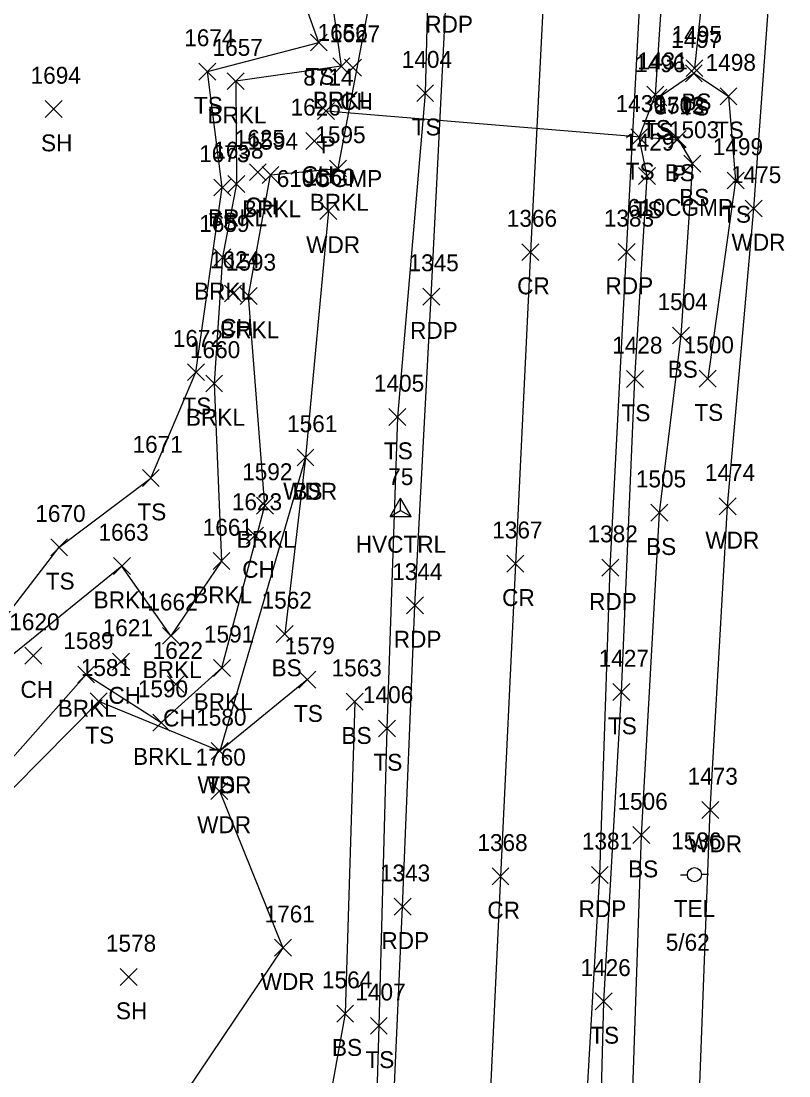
# Model space of a CAD drawing. Extents: x 1482574 to 1485769, y 580696 to 595649.
# Drawn here: x 1485133.4 to 1485224.3, y 582027 to 582151.9 of the extents above; entities that cross this region are included whole.
import ezdxf

# ---------------------------------------------------------------- set-up
doc = ezdxf.new("R2010")
doc.units = 0
for name, color, linetype in [('C_A', 7, 'Continuous'), ('C_I', 7, 'Continuous'), ('CPSM', 7, 'Continuous'), ('D_A', 7, 'Continuous'), ('D_C', 7, 'Continuous'), ('D_I', 7, 'Continuous'), ('D_TIC', 7, 'Continuous'), ('DCP', 7, 'Continuous'), ('L_A', 7, 'Continuous'), ('L_I', 7, 'Continuous'), ('L_TIC', 7, 'Continuous'), ('LAWA', 7, 'Continuous'), ('LAWE', 7, 'Continuous'), ('LELB', 7, 'Continuous'), ('P_A', 7, 'Continuous'), ('P_I', 7, 'Continuous'), ('P_TIC', 7, 'Continuous'), ('PET', 7, 'Continuous'), ('PRC', 7, 'Continuous'), ('U_A', 7, 'Continuous'), ('U_C', 7, 'Continuous'), ('U_I', 7, 'Continuous'), ('UP', 7, 'Continuous')]:
    doc.layers.add(name, color=color, linetype=linetype)

msp = doc.modelspace()

# ---------------------------------------------------------------- linework, layer by layer
at = {"layer": 'CPSM'}
for p, q in [((1485177.11, 582093.23), (1485178.36, 582095.39)), ((1485177.11, 582093.23), (1485178.36, 582095.39)), ((1485177.11, 582093.23), (1485178.36, 582095.39)), ((1485179.61, 582093.23), (1485178.36, 582095.39)), ((1485178.36, 582093.95), (1485178.36, 582095.39)), ((1485179.61, 582093.23), (1485178.36, 582095.39)), ((1485178.36, 582093.95), (1485178.36, 582095.39)), ((1485179.61, 582093.23), (1485178.36, 582095.39)), ((1485178.36, 582093.95), (1485178.36, 582095.39)), ((1485177.11, 582093.23), (1485178.36, 582093.95)), ((1485177.11, 582093.23), (1485178.36, 582093.95)), ((1485177.11, 582093.23), (1485178.36, 582093.95)), ((1485178.36, 582093.95), (1485178.36, 582093.95)), ((1485178.36, 582093.95), (1485179.61, 582093.23)), ((1485178.36, 582093.95), (1485178.36, 582093.95)), ((1485178.36, 582093.95), (1485179.61, 582093.23)), ((1485178.36, 582093.95), (1485178.36, 582093.95)), ((1485178.36, 582093.95), (1485179.61, 582093.23)), ((1485177.11, 582093.23), (1485179.61, 582093.23)), ((1485177.11, 582093.23), (1485179.61, 582093.23)), ((1485177.11, 582093.23), (1485179.61, 582093.23))]:
    msp.add_line(p, q, dxfattribs=at)
at = {"layer": 'D_TIC'}
for points in [[(1485168.54, 582140.23), (1485170.54, 582142.23)], [(1485170.54, 582140.23), (1485168.54, 582142.23)], [(1485210.06, 582136.81), (1485212.06, 582138.81)], [(1485212.06, 582136.81), (1485210.06, 582138.81)]]:
    msp.add_lwpolyline(points, dxfattribs=at)
at = {"layer": 'DCP'}
msp.add_lwpolyline([(1485169.54, 582141.23), (1485211.06, 582137.81)], dxfattribs=at)
at = {"layer": 'L_TIC'}
for points in [[(1485167.69, 582148.33), (1485169.69, 582150.33)], [(1485169.69, 582148.33), (1485167.69, 582150.33)], [(1485170.34, 582145.51), (1485172.34, 582147.51)], [(1485172.34, 582145.51), (1485170.34, 582147.51)], [(1485154.49, 582144.89), (1485156.49, 582146.89)], [(1485156.49, 582144.89), (1485154.49, 582146.89)], [(1485171.72, 582145.36), (1485173.72, 582147.36)], [(1485173.72, 582145.36), (1485171.72, 582147.36)], [(1485212.07, 582144.69), (1485214.07, 582146.69)], [(1485214.07, 582144.69), (1485212.07, 582146.69)], [(1485212.15, 582145.29), (1485214.14, 582147.29)], [(1485214.14, 582145.29), (1485212.15, 582147.29)], [(1485157.85, 582143.75), (1485159.85, 582145.75)], [(1485159.85, 582143.75), (1485157.85, 582145.75)], [(1485180.27, 582142.33), (1485182.27, 582144.33)], [(1485182.27, 582142.33), (1485180.27, 582144.33)], [(1485207.52, 582142.15), (1485209.52, 582144.15)], [(1485209.52, 582142.15), (1485207.52, 582144.15)], [(1485207.87, 582141.82), (1485209.87, 582143.82)], [(1485209.87, 582141.82), (1485207.87, 582143.82)], [(1485216.17, 582141.97), (1485218.17, 582143.97)], [(1485218.17, 582141.97), (1485216.17, 582143.97)], [(1485136.31, 582140.45), (1485138.31, 582142.45)], [(1485138.31, 582140.45), (1485136.31, 582142.45)], [(1485167.14, 582136.68), (1485169.14, 582138.68)], [(1485169.14, 582136.68), (1485167.14, 582138.68)], [(1485205.6, 582137.1), (1485207.6, 582139.1)], [(1485207.6, 582137.1), (1485205.6, 582139.1)], [(1485210.18, 582136.92), (1485212.18, 582138.92)], [(1485212.18, 582136.92), (1485210.18, 582138.92)], [(1485160.47, 582132.98), (1485162.47, 582134.98)], [(1485162.47, 582132.98), (1485160.47, 582134.98)], [(1485169.96, 582133.42), (1485171.96, 582135.42)], [(1485171.96, 582133.42), (1485169.96, 582135.42)], [(1485211.9, 582134), (1485213.9, 582136)], [(1485213.9, 582134), (1485211.9, 582136)], [(1485161.97, 582132.65), (1485163.96, 582134.65)], [(1485163.96, 582132.65), (1485161.97, 582134.65)], [(1485206.53, 582132.53), (1485208.53, 582134.53)], [(1485208.53, 582132.53), (1485206.53, 582134.53)], [(1485217.01, 582132), (1485219.01, 582134)], [(1485219.01, 582132), (1485217.01, 582134)], [(1485156.26, 582131.17), (1485158.26, 582133.17)], [(1485158.26, 582131.17), (1485156.26, 582133.17)], [(1485157.93, 582131.59), (1485159.93, 582133.59)], [(1485159.93, 582131.59), (1485157.93, 582133.59)], [(1485168.82, 582128.4), (1485170.82, 582130.4)], [(1485170.82, 582128.4), (1485168.82, 582130.4)], [(1485219.16, 582128.7), (1485221.16, 582130.69)], [(1485221.16, 582128.7), (1485219.16, 582130.69)], [(1485156.28, 582122.91), (1485158.28, 582124.91)], [(1485158.28, 582122.91), (1485156.28, 582124.91)], [(1485157.53, 582118.62), (1485159.53, 582120.62)], [(1485159.53, 582118.62), (1485157.53, 582120.62)], [(1485159.37, 582118.33), (1485161.37, 582120.33)], [(1485161.37, 582118.33), (1485159.37, 582120.33)], [(1485210.54, 582113.66), (1485212.54, 582115.66)], [(1485212.54, 582113.66), (1485210.54, 582115.66)], [(1485153.14, 582109.31), (1485155.14, 582111.31)], [(1485155.14, 582109.31), (1485153.14, 582111.31)], [(1485155.3, 582107.98), (1485157.3, 582109.98)], [(1485157.3, 582107.98), (1485155.3, 582109.98)], [(1485205.1, 582108.51), (1485207.1, 582110.51)], [(1485207.1, 582108.51), (1485205.1, 582110.51)], [(1485213.72, 582108.55), (1485215.72, 582110.55)], [(1485215.72, 582108.55), (1485213.72, 582110.55)], [(1485176.98, 582104.01), (1485178.98, 582106.01)], [(1485178.98, 582104.01), (1485176.98, 582106.01)], [(1485166.11, 582099.22), (1485168.1, 582101.22)], [(1485168.1, 582099.22), (1485166.11, 582101.22)], [(1485166.11, 582099.22), (1485168.1, 582101.22)], [(1485168.1, 582099.22), (1485166.11, 582101.22)], [(1485147.8, 582096.78), (1485149.8, 582098.78)], [(1485149.8, 582096.78), (1485147.8, 582098.78)], [(1485161.31, 582093.53), (1485163.3, 582095.53)], [(1485163.3, 582093.53), (1485161.31, 582095.53)], [(1485216.07, 582093.44), (1485218.07, 582095.44)], [(1485218.07, 582093.44), (1485216.07, 582095.44)], [(1485207.98, 582092.68), (1485209.98, 582094.68)], [(1485209.98, 582092.68), (1485207.98, 582094.68)], [(1485160.13, 582089.99), (1485162.13, 582091.98)], [(1485162.13, 582089.99), (1485160.13, 582091.98)], [(1485136.95, 582088.59), (1485138.95, 582090.59)], [(1485138.95, 582088.59), (1485136.95, 582090.59)], [(1485156.16, 582086.96), (1485158.16, 582088.96)], [(1485158.16, 582086.96), (1485156.16, 582088.96)], [(1485144.38, 582086.37), (1485146.38, 582088.37)], [(1485146.38, 582086.37), (1485144.38, 582088.37)], [(1485150.18, 582078.12), (1485152.18, 582080.11)], [(1485152.18, 582078.12), (1485150.18, 582080.11)], [(1485163.65, 582078.34), (1485165.65, 582080.33)], [(1485165.65, 582078.34), (1485163.65, 582080.33)], [(1485133.88, 582075.77), (1485135.88, 582077.77)], [(1485135.88, 582075.77), (1485133.88, 582077.77)], [(1485144.28, 582075.07), (1485146.28, 582077.07)], [(1485146.28, 582075.07), (1485144.28, 582077.07)], [(1485156.22, 582074.32), (1485158.22, 582076.32)], [(1485158.22, 582074.32), (1485156.22, 582076.32)], [(1485140.14, 582073.54), (1485142.14, 582075.54)], [(1485142.14, 582073.54), (1485140.14, 582075.54)], [(1485150.76, 582072.39), (1485152.76, 582074.39)], [(1485152.76, 582072.39), (1485150.76, 582074.39)], [(1485166.33, 582072.93), (1485168.33, 582074.93)], [(1485168.33, 582072.93), (1485166.33, 582074.93)], [(1485203.5, 582071.46), (1485205.5, 582073.46)], [(1485205.5, 582071.46), (1485203.5, 582073.46)], [(1485141.63, 582070.36), (1485143.63, 582072.36)], [(1485143.63, 582070.36), (1485141.63, 582072.36)], [(1485171.93, 582070.32), (1485173.93, 582072.32)], [(1485173.93, 582070.32), (1485171.93, 582072.32)], [(1485149.04, 582067.84), (1485151.04, 582069.84)], [(1485151.04, 582067.84), (1485149.04, 582069.84)], [(1485175.74, 582067.15), (1485177.74, 582069.15)], [(1485177.74, 582067.15), (1485175.74, 582069.15)], [(1485155.95, 582064.48), (1485157.95, 582066.48)], [(1485157.95, 582064.48), (1485155.95, 582066.48)], [(1485155.95, 582064.48), (1485157.95, 582066.48)], [(1485157.95, 582064.48), (1485155.95, 582066.48)], [(1485155.92, 582059.76), (1485157.92, 582061.76)], [(1485157.92, 582059.76), (1485155.92, 582061.76)], [(1485214.03, 582057.5), (1485216.03, 582059.5)], [(1485216.03, 582057.5), (1485214.03, 582059.5)], [(1485205.85, 582054.53), (1485207.85, 582056.53)], [(1485207.85, 582054.53), (1485205.85, 582056.53)], [(1485163.44, 582041.2), (1485165.43, 582043.2)], [(1485165.43, 582041.2), (1485163.44, 582043.2)], [(1485145.18, 582037.74), (1485147.18, 582039.74)], [(1485147.18, 582037.74), (1485145.18, 582039.74)], [(1485201.4, 582034.85), (1485203.4, 582036.85)], [(1485203.4, 582034.85), (1485201.4, 582036.85)], [(1485170.8, 582033.4), (1485172.8, 582035.4)], [(1485172.8, 582033.4), (1485170.8, 582035.4)], [(1485174.79, 582031.96), (1485176.79, 582033.96)], [(1485176.79, 582031.96), (1485174.79, 582033.96)]]:
    msp.add_lwpolyline(points, dxfattribs=at)
at = {"layer": 'LAWA'}
for points in [[(1485207.14, 581842.19), (1485209.3, 581873.94), (1485212.4, 581914.05), (1485215, 581947.41), (1485214.38, 581982.49), (1485213.5, 582018.76), (1485215.02, 582058.5), (1485217.07, 582094.44), (1485220.16, 582129.69), (1485222.69, 582164.53), (1485228.33, 582204.07), (1485228.99, 582241.88)], [(1485169.82, 582129.4), (1485167.1, 582100.22), (1485156.95, 582065.48)], [(1485156.92, 582060.76), (1485164.44, 582042.2), (1485101.4, 581948.62), (1485130.03, 581885.05), (1485148.38, 581838.92)]]:
    msp.add_lwpolyline(points, dxfattribs=at)
at = {"layer": 'LAWE'}
for points in [[(1485170.69, 582309.08), (1485153.21, 582310.76), (1485130.29, 582302.62), (1485123.09, 582299.49), (1485120.54, 582286.49), (1485123.5, 582278.34), (1485131.5, 582270.72), (1485144.03, 582266.75), (1485154.88, 582242.22), (1485159.22, 582222.92), (1485148.53, 582200.7), (1485150.55, 582173.44), (1485168.89, 582163.93), (1485171.34, 582146.51), (1485158.85, 582144.75), (1485158.93, 582132.59), (1485157.28, 582123.91), (1485156.3, 582108.98), (1485157.16, 582087.96), (1485151.18, 582079.11), (1485145.38, 582087.37), (1485129.84, 582074.78), (1485111.65, 582056.66), (1485093.6, 582042.4)], [(1485102.04, 582042.8), (1485124.29, 582055.53), (1485141.14, 582074.54), (1485150.04, 582068.84), (1485157.22, 582075.32), (1485162.3, 582094.53), (1485160.37, 582119.33), (1485162.97, 582133.65), (1485170.96, 582134.42), (1485175.45, 582158.02), (1485168.06, 582170.03), (1485154.36, 582176.42), (1485153.38, 582200.18), (1485162.9, 582220.04), (1485158.32, 582247.39), (1485144.76, 582271.03), (1485130.69, 582275.44), (1485124.94, 582289.99), (1485140.55, 582299.94), (1485169.91, 582303.34)]]:
    msp.add_lwpolyline(points, dxfattribs=at)
at = {"layer": 'LELB'}
for points in [[(1485086.26, 582448.72), (1485109.16, 582421.47), (1485134.85, 582391.85), (1485154.93, 582361.1), (1485163.91, 582350.39), (1485172.69, 582324.11), (1485180.27, 582288.22), (1485183.46, 582251.5), (1485183.69, 582215.19), (1485182.17, 582178.89), (1485181.27, 582143.33), (1485177.98, 582105.01), (1485176.74, 582068.15), (1485175.79, 582032.96), (1485174.69, 581995.51), (1485171.97, 581958.58), (1485171.35, 581920.7), (1485169.2, 581883.5), (1485167.12, 581847.49)], [(1485100.27, 582055.63), (1485110.08, 582058.51), (1485124.08, 582071.56), (1485137.95, 582089.59), (1485148.8, 582097.78), (1485154.14, 582110.31), (1485157.26, 582132.17), (1485155.49, 582145.89), (1485168.69, 582149.33), (1485164.06, 582162.21), (1485147.52, 582170.61), (1485143.18, 582191.84), (1485156.63, 582218.88), (1485154.27, 582241.36), (1485136.96, 582267.16), (1485123.3, 582273.77), (1485116.72, 582290.83), (1485121.2, 582301.75), (1485133.28, 582305.77), (1485150.99, 582313.45), (1485164.94, 582314.76), (1485171.47, 582309.52)], [(1485222.22, 582264.2), (1485221.11, 582240.02), (1485219.57, 582221.71), (1485220.85, 582207.58), (1485215.91, 582172.31), (1485213.15, 582146.29)], [(1485213.13, 581958), (1485206.44, 581957.22), (1485199.12, 581963.07), (1485201.47, 581999.68), (1485202.4, 582035.85), (1485204.5, 582072.46), (1485206.1, 582109.51), (1485207.53, 582133.53), (1485206.6, 582138.1), (1485208.52, 582143.15), (1485210.94, 582179.4)], [(1485208.87, 582142.82), (1485213.07, 582145.69), (1485217.17, 582142.97), (1485218.01, 582133), (1485214.72, 582109.55)], [(1485211.18, 582137.92), (1485212.9, 582135), (1485211.54, 582114.66), (1485208.98, 582093.68), (1485206.85, 582055.53), (1485205.47, 582015.01), (1485205.83, 581984.5), (1485205.19, 581962.26), (1485210.7, 581961.02)], [(1485167.1, 582100.22), (1485164.65, 582079.33)], [(1485167.33, 582073.93), (1485156.95, 582065.48), (1485142.63, 582071.36), (1485125.7, 582054.26), (1485101.89, 582035.3), (1485098.7, 582002.19)], [(1485172.93, 582071.32), (1485171.8, 582034.4), (1485164.49, 581993.93), (1485164.47, 581955.33), (1485161.09, 581909.08), (1485158.77, 581862.05), (1485153.38, 581821.57)]]:
    msp.add_lwpolyline(points, dxfattribs=at)
at = {"layer": 'P_TIC'}
for points in [[(1485192.73, 582123.53), (1485194.73, 582125.52)], [(1485194.73, 582123.53), (1485192.73, 582125.52)], [(1485204.12, 582123.54), (1485206.12, 582125.54)], [(1485206.12, 582123.54), (1485204.12, 582125.54)], [(1485180.99, 582118.26), (1485182.99, 582120.26)], [(1485182.99, 582118.26), (1485180.99, 582120.26)], [(1485190.95, 582086.64), (1485192.95, 582088.64)], [(1485192.95, 582086.64), (1485190.95, 582088.64)], [(1485202.18, 582086.18), (1485204.18, 582088.18)], [(1485204.18, 582086.18), (1485202.18, 582088.18)], [(1485179.06, 582081.71), (1485181.06, 582083.71)], [(1485181.06, 582081.71), (1485179.06, 582083.71)], [(1485189.19, 582049.65), (1485191.19, 582051.65)], [(1485191.19, 582049.65), (1485189.19, 582051.65)], [(1485200.94, 582049.82), (1485202.94, 582051.82)], [(1485202.94, 582049.82), (1485200.94, 582051.82)], [(1485177.6, 582046.05), (1485179.6, 582048.05)], [(1485179.6, 582046.05), (1485177.6, 582048.05)]]:
    msp.add_lwpolyline(points, dxfattribs=at)
at = {"layer": 'PET'}
for points in [[(1485192.11, 581830.95), (1485193.73, 581867.91), (1485194.94, 581905.19), (1485196.49, 581941.47), (1485198.47, 581977.8), (1485199.85, 582014.54), (1485201.94, 582050.82), (1485203.18, 582087.18), (1485205.12, 582124.54), (1485207.06, 582161.38), (1485208.85, 582198.4), (1485209.89, 582235.49), (1485209.38, 582272.64), (1485204.65, 582311.64), (1485195.27, 582347.62), (1485180.76, 582381.17), (1485161.8, 582413.22), (1485138.07, 582446.52), (1485117.46, 582473.15)], [(1485169.12, 581831.45), (1485170.32, 581867.28), (1485172.03, 581902.79), (1485173.6, 581938.27), (1485175.25, 581974.03), (1485176.93, 582010.15), (1485178.6, 582047.05), (1485180.06, 582082.71), (1485181.99, 582119.26), (1485183.79, 582155.49), (1485184.61, 582191.74), (1485185.43, 582228.42), (1485184.46, 582264.59), (1485179.73, 582300.45), (1485171.37, 582335.39), (1485157.78, 582369.57), (1485140.1, 582401.86), (1485120.36, 582429.63), (1485099.05, 582457.32)]]:
    msp.add_lwpolyline(points, dxfattribs=at)
at = {"layer": 'PRC'}
msp.add_lwpolyline([(1485108.02, 582465.15), (1485108.02, 582465.14), (1485149.79, 582407.48), (1485166.92, 582377.32), (1485181.4, 582344.02), (1485191.72, 582309.19), (1485197.06, 582272.58), (1485198.41, 582235.33), (1485197.35, 582197.87), (1485195.61, 582161.03), (1485193.73, 582124.53), (1485191.95, 582087.64), (1485190.19, 582050.65), (1485188.41, 582012.94), (1485186.85, 581975.84), (1485185.26, 581938.82), (1485183.58, 581901.19), (1485182.04, 581863.11), (1485180.48, 581826.27)], dxfattribs=at)
at = {"layer": 'UP'}
for p, q in [((1485211.48, 582050.84), (1485212.3, 582050.84)), ((1485213.14, 582050.85), (1485213.14, 582050.85)), ((1485214.8, 582050.85), (1485213.97, 582050.85)), ((1485213.97, 582050.85), (1485213.97, 582050.85)), ((1485214.8, 582050.85), (1485214.8, 582050.85))]:
    msp.add_line(p, q, dxfattribs=at)
msp.add_circle((1485213.14, 582050.85), 0.833, dxfattribs=at)

# ---------------------------------------------------------------- texts
at = {"layer": 'C_A'}
msp.add_text('HVCTRL', height=2, dxfattribs=at).set_placement((1485173.06, 582088.95))
msp.add_text('HVCTRL', height=2, dxfattribs=at).set_placement((1485173.06, 582088.95))
msp.add_text('HVCTRL', height=2, dxfattribs=at).set_placement((1485173.06, 582088.95))
at = {"layer": 'C_I'}
msp.add_text('75', height=2, dxfattribs=at).set_placement((1485176.9, 582096.95))
msp.add_text('75', height=2, dxfattribs=at).set_placement((1485176.9, 582096.95))
msp.add_text('75', height=2, dxfattribs=at).set_placement((1485176.9, 582096.95))
at = {"layer": 'D_A'}
for p in [(1485168.91, 582136.23), (1485210.44, 582132.81)]:
    msp.add_text('P', height=2, dxfattribs=at).set_placement(p)
at = {"layer": 'D_C'}
for p in [(1485163.7, 582132.23), (1485205.22, 582128.81)]:
    msp.add_text('610CGMP', height=2, dxfattribs=at).set_placement(p)
at = {"layer": 'D_I'}
for s, p in [('8714', (1485166.84, 582144.23)), ('8715', (1485208.37, 582140.81))]:
    msp.add_text(s, height=2, dxfattribs=at).set_placement(p)
at = {"layer": 'L_A'}
for s, p in [('TS', (1485167.1, 582144.33)), ('TS', (1485153.9, 582140.89)), ('BRKL', (1485167.98, 582141.51)), ('CH', (1485171.21, 582141.36)), ('TS', (1485211.48, 582140.69)), ('BS', (1485211.59, 582141.29)), ('BRKL', (1485155.5, 582139.75)), ('TS', (1485179.68, 582138.33)), ('TS', (1485206.93, 582138.15)), ('TS', (1485215.58, 582137.97)), ('TS', (1485207.28, 582137.82)), ('SH', (1485135.8, 582136.45)), ('TS', (1485205.01, 582133.1)), ('BS', (1485209.62, 582132.92)), ('CH', (1485166.63, 582132.68)), ('BRKL', (1485167.61, 582129.42)), ('BS', (1485211.34, 582130)), ('BRKL', (1485159.61, 582128.65)), ('CH', (1485159.96, 582128.98)), ('TS', (1485205.94, 582128.53)), ('TS', (1485216.42, 582128)), ('TS', (1485155.67, 582127.17)), ('BRKL', (1485155.57, 582127.59)), ('WDR', (1485167.18, 582124.4)), ('WDR', (1485217.53, 582124.69)), ('BRKL', (1485153.92, 582118.91)), ('CH', (1485157.01, 582114.62)), ('BRKL', (1485157.01, 582114.33)), ('BS', (1485209.98, 582109.66)), ('TS', (1485152.55, 582105.31)), ('TS', (1485204.51, 582104.51)), ('TS', (1485213.13, 582104.55)), ('BRKL', (1485152.95, 582103.98)), ('TS', (1485176.39, 582100.01)), ('WDR', (1485164.47, 582095.22)), ('BS', (1485165.55, 582095.22)), ('TS', (1485147.21, 582092.78)), ('BRKL', (1485158.95, 582089.53)), ('WDR', (1485214.43, 582089.44)), ('BS', (1485207.42, 582088.68)), ('CH', (1485159.62, 582085.98)), ('TS', (1485136.36, 582084.59)), ('BRKL', (1485142.03, 582082.37)), ('BRKL', (1485153.81, 582082.96)), ('BS', (1485163.09, 582074.33)), ('BRKL', (1485147.83, 582074.11)), ('CH', (1485133.37, 582071.77)), ('CH', (1485143.77, 582071.07)), ('BRKL', (1485137.78, 582069.54)), ('BRKL', (1485153.87, 582070.32)), ('CH', (1485150.25, 582068.39)), ('TS', (1485165.74, 582068.93)), ('TS', (1485202.91, 582067.46)), ('TS', (1485141.04, 582066.36)), ('BS', (1485171.37, 582066.32)), ('BRKL', (1485146.69, 582063.84)), ('TS', (1485175.15, 582063.15)), ('WDR', (1485154.32, 582060.48)), ('TS', (1485155.36, 582060.48)), ('WDR', (1485154.28, 582055.76)), ('WDR', (1485212.39, 582053.5)), ('BS', (1485205.29, 582050.53)), ('WDR', (1485161.8, 582037.2)), ('SH', (1485144.67, 582033.74)), ('TS', (1485200.81, 582030.85)), ('BS', (1485170.24, 582029.4)), ('TS', (1485174.2, 582027.96))]:
    msp.add_text(s, height=2, dxfattribs=at).set_placement(p)
at = {"layer": 'L_I'}
for s, p in [('1656', (1485168.54, 582149.51)), ('1627', (1485169.98, 582149.36)), ('1495', (1485210.45, 582149.29)), ('1674', (1485152.75, 582148.89)), ('1497', (1485210.38, 582148.69)), ('1657', (1485156.11, 582147.75)), ('1404', (1485178.5, 582146.33)), ('1496', (1485206.12, 582145.82)), ('1431', (1485206.39, 582146.15)), ('1498', (1485214.47, 582145.97)), ('1694', (1485134.57, 582144.45)), ('1626', (1485165.34, 582140.68)), ('1430', (1485203.82, 582141.1)), ('1502', (1485208.41, 582140.92)), ('1503', (1485210.12, 582138)), ('1625', (1485158.73, 582136.98)), ('1594', (1485160.27, 582136.65)), ('1595', (1485168.27, 582137.42)), ('1658', (1485156.19, 582135.59)), ('1429', (1485204.83, 582136.53)), ('1499', (1485215.31, 582136)), ('1673', (1485154.52, 582135.17)), ('1560', (1485166.99, 582132.4)), ('1475', (1485217.47, 582132.69)), ('1659', (1485154.53, 582126.91)), ('1624', (1485155.79, 582122.62)), ('1593', (1485157.67, 582122.33)), ('1504', (1485208.77, 582117.66)), ('1672', (1485151.4, 582113.31)), ('1660', (1485153.43, 582111.98)), ('1428', (1485203.41, 582112.51)), ('1500', (1485211.86, 582112.55)), ('1405', (1485175.21, 582108.01)), ('1561', (1485164.93, 582103.22)), ('1561', (1485164.93, 582103.22)), ('1671', (1485146.63, 582100.78)), ('1592', (1485159.61, 582097.53)), ('1505', (1485206.21, 582096.68)), ('1474', (1485214.37, 582097.44)), ('1623', (1485158.39, 582093.98)), ('1670', (1485135.13, 582092.59)), ('1661', (1485154.94, 582090.96)), ('1663', (1485142.6, 582090.37)), ('1662', (1485148.39, 582082.11)), ('1562', (1485161.91, 582082.33)), ('1620', (1485132.05, 582079.77)), ('1621', (1485143.1, 582079.07)), ('1591', (1485155.09, 582078.32)), ('1589', (1485138.44, 582077.54)), ('1579', (1485164.63, 582076.93)), ('1622', (1485149.02, 582076.39)), ('1427', (1485201.81, 582075.46)), ('1581', (1485140.51, 582074.36)), ('1563', (1485170.19, 582074.32)), ('1590', (1485147.26, 582071.84)), ('1406', (1485173.91, 582071.15)), ('1580', (1485154.17, 582068.48)), ('1580', (1485154.17, 582068.48)), ('1760', (1485154.09, 582063.76)), ('1473', (1485212.33, 582061.5)), ('1506', (1485204.03, 582058.53)), ('1761', (1485162.26, 582045.2)), ('1578', (1485143.48, 582041.74)), ('1426', (1485199.66, 582038.85)), ('1564', (1485169.06, 582037.4)), ('1407', (1485173.01, 582035.96))]:
    msp.add_text(s, height=2, dxfattribs=at).set_placement(p)
at = {"layer": 'P_A'}
for s, p in [('RDP', (1485181.28, 582150.49)), ('CR', (1485192.16, 582119.53)), ('RDP', (1485202.61, 582119.54)), ('RDP', (1485179.48, 582114.26)), ('CR', (1485190.38, 582082.64)), ('RDP', (1485200.67, 582082.18)), ('RDP', (1485177.55, 582077.71)), ('CR', (1485188.63, 582045.65)), ('RDP', (1485199.43, 582045.82)), ('RDP', (1485176.09, 582042.05))]:
    msp.add_text(s, height=2, dxfattribs=at).set_placement(p)
at = {"layer": 'P_I'}
for s, p in [('1366', (1485190.93, 582127.52)), ('1383', (1485202.42, 582127.54)), ('1345', (1485179.3, 582122.26)), ('1367', (1485189.21, 582090.64)), ('1382', (1485200.49, 582090.18)), ('1344', (1485177.37, 582085.71)), ('1368', (1485187.45, 582053.65)), ('1381', (1485199.82, 582053.82)), ('1343', (1485175.91, 582050.05))]:
    msp.add_text(s, height=2, dxfattribs=at).set_placement(p)
at = {"layer": 'U_A'}
msp.add_text('TEL', height=2, dxfattribs=at).set_placement((1485210.69, 582045.85))
at = {"layer": 'U_C'}
msp.add_text('5/62', height=2, dxfattribs=at).set_placement((1485209.75, 582041.85))
at = {"layer": 'U_I'}
msp.add_text('1536', height=2, dxfattribs=at).set_placement((1485210.39, 582053.85))

doc.saveas('drawing.dxf')
